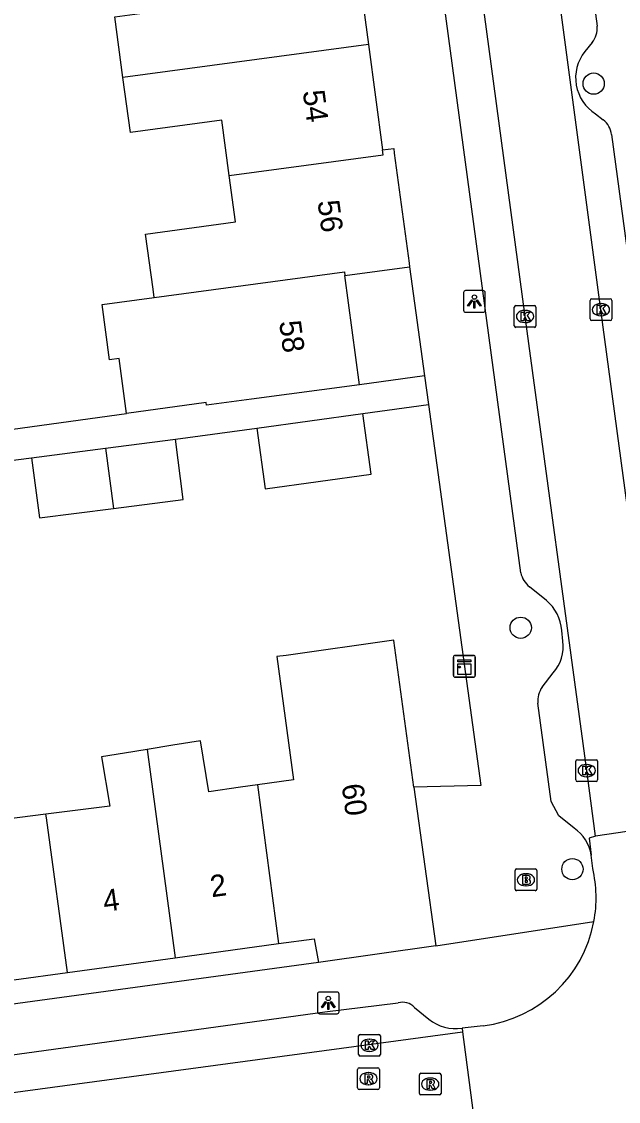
# Model space of a CAD drawing. Extents: x 163150 to 163546, y 380933 to 381635.
# Drawn here: x 163457.89 to 163485.3, y 381316.42 to 381366.01 of the extents above; entities that cross this region are included whole.
import ezdxf

# ---------------------------------------------------------------- set-up
doc = ezdxf.new("R2010")
doc.units = 0
for name, color, linetype in [('IMGEO_Boom', 7, 'Continuous'), ('IMGEO_Brandkraan', 7, 'Continuous'), ('IMGEO_Kast', 7, 'Continuous'), ('IMGEO_Kolk', 7, 'Continuous'), ('IMGEO_Lichtpunt', 7, 'Continuous'), ('IMGEO_Pand', 7, 'Continuous'), ('IMGEO_Pand_nummerreeks', 7, 'Continuous'), ('IMGEO_Rijbaan_lokaal_open', 7, 'Continuous'), ('IMGEO_Rioolput', 7, 'Continuous'), ('IMGEO_Voetpad_open', 7, 'Continuous')]:
    doc.layers.add(name, color=color, linetype=linetype)

msp = doc.modelspace()

# ---------------------------------------------------------------- linework, layer by layer
at = {"layer": 'IMGEO_Boom'}
for centre in [(163484.163, 381363.164), (163480.812, 381338.174), (163483.189, 381327.09)]:
    msp.add_circle(centre, 0.489, dxfattribs=at)
at = {"layer": 'IMGEO_Brandkraan'}
for p, q in [((163480.551, 381326.176), (163480.551, 381327.028)), ((163480.626, 381327.102), (163481.478, 381327.102)), ((163481.039, 381326.882), (163481.064, 381326.882)), ((163481.552, 381327.028), (163481.552, 381326.176)), ((163481.062, 381326.322), (163481.037, 381326.322)), ((163481.478, 381326.102), (163480.626, 381326.102))]:
    msp.add_line(p, q, dxfattribs=at)
for points in [[(163480.551, 381326.176), (163480.551, 381327.028)], [(163480.626, 381327.102), (163481.478, 381327.102)], [(163480.899, 381326.802), (163480.899, 381326.402), (163481.112, 381326.402)], [(163481.13, 381326.802), (163480.899, 381326.802)], [(163481.078, 381326.721), (163481.024, 381326.721), (163481.024, 381326.645)], [(163481.552, 381327.028), (163481.552, 381326.176)], [(163481.024, 381326.645), (163481.077, 381326.645)], [(163481.086, 381326.569), (163481.024, 381326.569), (163481.024, 381326.488)], [(163481.024, 381326.488), (163481.086, 381326.488)], [(163481.478, 381326.102), (163480.626, 381326.102)]]:
    msp.add_lwpolyline(points, dxfattribs=at)
for centre, radius, start, end in [((163480.628, 381327.026), 0.0765, 91.552, 178.448), ((163480.628, 381327.026), 0.0765, 91.552, 178.448), ((163481.079, 381326.683), 0.0379, 267.8285, 90.9355), ((163481.134, 381326.657), 0.145, 59.4692, 91.5367), ((163481.159, 381326.704), 0.0922, 285.5137, 58.1501), ((163481.476, 381327.026), 0.0765, 1.552, 88.448), ((163481.476, 381327.026), 0.0765, 1.552, 88.448), ((163480.628, 381326.178), 0.0765, 181.552, 268.448), ((163480.628, 381326.178), 0.0765, 181.552, 268.448), ((163481.087, 381326.528), 0.0404, 269.8759, 90.5077), ((163481.118, 381326.653), 0.251, 268.6676, 293.5347), ((163481.164, 381326.512), 0.105, 301.3115, 78.989), ((163481.476, 381326.178), 0.0765, 271.552, 358.448), ((163481.476, 381326.178), 0.0765, 271.552, 358.448)]:
    msp.add_arc(centre, radius, start, end, dxfattribs=at)
for centre, major_axis, ratio, start_param, end_param in [((163481.038, 381326.602), (-0.387, 0.002), 0.722429, 4.712389, 7.853982), ((163481.063, 381326.602), (-0.39, 0.002), 0.717154, 1.570796, 4.712389)]:
    msp.add_ellipse(centre, major_axis=major_axis, ratio=ratio, start_param=start_param, end_param=end_param, dxfattribs=at)
at = {"layer": 'IMGEO_Kast'}
for p, q in [((163477.725, 381335.98), (163477.725, 381336.821)), ((163477.725, 381336.821), (163477.725, 381335.98)), ((163477.8, 381336.905), (163478.641, 381336.905)), ((163478.641, 381336.905), (163477.8, 381336.905)), ((163478.725, 381336.83), (163478.725, 381335.989)), ((163478.725, 381335.989), (163478.725, 381336.83)), ((163478.65, 381335.905), (163477.809, 381335.905)), ((163477.809, 381335.905), (163478.65, 381335.905))]:
    msp.add_line(p, q, dxfattribs=at)
for points in [[(163477.92, 381336.695), (163478.52, 381336.695), (163478.52, 381336.61), (163477.92, 381336.61), (163477.92, 381336.695)], [(163477.92, 381336.52), (163478.52, 381336.52), (163478.52, 381336.031), (163477.92, 381336.031), (163477.92, 381336.52)]]:
    msp.add_lwpolyline(points, dxfattribs=at)
msp.add_circle((163478.004, 381336.369), 0.0377, dxfattribs=at)
for centre, start, end in [((163477.803, 381336.827), 92.4484, 184.2845), ((163477.803, 381336.827), 92.4484, 184.2845), ((163478.647, 381336.827), 2.4484, 94.2845), ((163478.647, 381336.827), 2.4484, 94.2845), ((163477.803, 381335.983), 182.4484, 274.2845), ((163477.803, 381335.983), 182.4484, 274.2845), ((163478.647, 381335.983), 272.4484, 4.2845), ((163478.647, 381335.983), 272.4484, 4.2845)]:
    msp.add_arc(centre, 0.0779, start, end, dxfattribs=at)
at = {"layer": 'IMGEO_Kolk'}
for p, q in [((163480.587, 381352.972), (163481.439, 381352.972)), ((163483.996, 381352.357), (163483.996, 381353.209)), ((163484.071, 381353.283), (163484.923, 381353.283)), ((163484.484, 381353.063), (163484.509, 381353.063)), ((163484.997, 381353.209), (163484.997, 381352.357)), ((163480.512, 381352.046), (163480.512, 381352.898)), ((163481, 381352.752), (163481.025, 381352.752)), ((163481.513, 381352.898), (163481.513, 381352.046)), ((163484.507, 381352.503), (163484.482, 381352.503)), ((163481.439, 381351.972), (163480.587, 381351.972)), ((163481.023, 381352.192), (163480.998, 381352.192)), ((163484.923, 381352.283), (163484.071, 381352.283)), ((163483.419, 381332.116), (163484.271, 381332.116)), ((163483.344, 381331.19), (163483.344, 381332.042)), ((163483.832, 381331.896), (163483.857, 381331.896)), ((163484.345, 381332.042), (163484.345, 381331.19)), ((163483.855, 381331.336), (163483.83, 381331.336)), ((163484.271, 381331.116), (163483.419, 381331.116)), ((163473.366, 381318.577), (163473.366, 381319.429)), ((163473.441, 381319.503), (163474.293, 381319.503)), ((163473.854, 381319.283), (163473.879, 381319.283)), ((163474.367, 381319.429), (163474.367, 381318.577)), ((163474.293, 381318.503), (163473.441, 381318.503)), ((163473.877, 381318.723), (163473.852, 381318.723))]:
    msp.add_line(p, q, dxfattribs=at)
for points in [[(163480.587, 381352.972), (163481.439, 381352.972)], [(163483.996, 381352.357), (163483.996, 381353.209)], [(163484.071, 381353.283), (163484.923, 381353.283)], [(163484.317, 381352.983), (163484.44, 381352.983), (163484.44, 381352.832), (163484.57, 381352.983), (163484.734, 381352.983), (163484.588, 381352.832), (163484.741, 381352.583), (163484.589, 381352.583), (163484.504, 381352.747), (163484.44, 381352.68), (163484.44, 381352.583), (163484.317, 381352.583), (163484.317, 381352.983)], [(163484.997, 381353.209), (163484.997, 381352.357)], [(163480.512, 381352.046), (163480.512, 381352.898)], [(163480.833, 381352.672), (163480.956, 381352.672), (163480.956, 381352.521), (163481.086, 381352.672), (163481.25, 381352.672), (163481.104, 381352.521), (163481.257, 381352.272), (163481.105, 381352.272), (163481.02, 381352.436), (163480.956, 381352.369), (163480.956, 381352.272), (163480.833, 381352.272), (163480.833, 381352.672)], [(163481.513, 381352.898), (163481.513, 381352.046)], [(163481.439, 381351.972), (163480.587, 381351.972)], [(163484.923, 381352.283), (163484.071, 381352.283)], [(163483.419, 381332.116), (163484.271, 381332.116)], [(163483.344, 381331.19), (163483.344, 381332.042)], [(163483.665, 381331.816), (163483.788, 381331.816), (163483.788, 381331.665), (163483.918, 381331.816), (163484.082, 381331.816), (163483.936, 381331.665), (163484.089, 381331.416), (163483.937, 381331.416), (163483.852, 381331.58), (163483.788, 381331.513), (163483.788, 381331.416), (163483.665, 381331.416), (163483.665, 381331.816)], [(163484.345, 381332.042), (163484.345, 381331.19)], [(163484.271, 381331.116), (163483.419, 381331.116)], [(163473.366, 381318.577), (163473.366, 381319.429)], [(163473.441, 381319.503), (163474.293, 381319.503)], [(163474.367, 381319.429), (163474.367, 381318.577)], [(163473.687, 381319.203), (163473.81, 381319.203), (163473.81, 381319.052), (163473.94, 381319.203), (163474.104, 381319.203), (163473.958, 381319.052), (163474.111, 381318.803), (163473.959, 381318.803), (163473.874, 381318.967), (163473.81, 381318.9), (163473.81, 381318.803), (163473.687, 381318.803), (163473.687, 381319.203)], [(163474.293, 381318.503), (163473.441, 381318.503)]]:
    msp.add_lwpolyline(points, dxfattribs=at)
for centre, start, end in [((163480.589, 381352.896), 91.552, 178.448), ((163480.589, 381352.896), 91.552, 178.448), ((163481.437, 381352.896), 1.552, 88.448), ((163481.437, 381352.896), 1.552, 88.448), ((163484.073, 381353.207), 91.552, 178.448), ((163484.073, 381353.207), 91.552, 178.448), ((163484.921, 381353.207), 1.552, 88.448), ((163484.921, 381353.207), 1.552, 88.448), ((163480.589, 381352.048), 181.552, 268.448), ((163480.589, 381352.048), 181.552, 268.448), ((163481.437, 381352.048), 271.552, 358.448), ((163481.437, 381352.048), 271.552, 358.448), ((163484.073, 381352.359), 181.552, 268.448), ((163484.073, 381352.359), 181.552, 268.448), ((163484.921, 381352.359), 271.552, 358.448), ((163484.921, 381352.359), 271.552, 358.448), ((163483.421, 381332.04), 91.552, 178.448), ((163483.421, 381332.04), 91.552, 178.448), ((163484.269, 381332.04), 1.552, 88.448), ((163484.269, 381332.04), 1.552, 88.448), ((163483.421, 381331.192), 181.552, 268.448), ((163483.421, 381331.192), 181.552, 268.448), ((163484.269, 381331.192), 271.552, 358.448), ((163484.269, 381331.192), 271.552, 358.448), ((163473.443, 381319.427), 91.552, 178.448), ((163473.443, 381319.427), 91.552, 178.448), ((163474.291, 381319.427), 1.552, 88.448), ((163474.291, 381319.427), 1.552, 88.448), ((163473.443, 381318.579), 181.552, 268.448), ((163473.443, 381318.579), 181.552, 268.448), ((163474.291, 381318.579), 271.552, 358.448), ((163474.291, 381318.579), 271.552, 358.448)]:
    msp.add_arc(centre, 0.0765, start, end, dxfattribs=at)
for centre, major_axis, ratio, start_param, end_param in [((163484.483, 381352.783), (-0.387, 0.002), 0.722429, 4.712389, 7.853982), ((163484.508, 381352.783), (-0.39, 0.002), 0.717154, 1.570796, 4.712389), ((163480.999, 381352.472), (-0.387, 0.002), 0.722429, 4.712389, 7.853982), ((163481.024, 381352.472), (-0.39, 0.002), 0.717154, 1.570796, 4.712389), ((163483.831, 381331.616), (-0.387, 0.002), 0.722429, 4.712389, 7.853982), ((163483.856, 381331.616), (-0.39, 0.002), 0.717154, 1.570796, 4.712389), ((163473.853, 381319.003), (-0.387, 0.002), 0.722429, 4.712389, 7.853982), ((163473.878, 381319.003), (-0.39, 0.002), 0.717154, 1.570796, 4.712389)]:
    msp.add_ellipse(centre, major_axis=major_axis, ratio=ratio, start_param=start_param, end_param=end_param, dxfattribs=at)
at = {"layer": 'IMGEO_Lichtpunt'}
for p, q in [((163478.187, 381353.565), (163478.187, 381352.758)), ((163478.187, 381353.565), (163478.187, 381352.758)), ((163479.089, 381353.66), (163478.281, 381353.66)), ((163479.089, 381353.66), (163478.281, 381353.66)), ((163479.183, 381352.758), (163479.183, 381353.565)), ((163479.183, 381352.758), (163479.183, 381353.565)), ((163478.281, 381352.664), (163479.089, 381352.664)), ((163478.281, 381352.664), (163479.089, 381352.664)), ((163471.475, 381321.352), (163471.475, 381320.545)), ((163471.475, 381321.352), (163471.475, 381320.545)), ((163472.377, 381321.447), (163471.569, 381321.447)), ((163472.377, 381321.447), (163471.569, 381321.447)), ((163472.471, 381320.545), (163472.471, 381321.352)), ((163472.471, 381320.545), (163472.471, 381321.352)), ((163471.569, 381320.451), (163472.377, 381320.451)), ((163471.569, 381320.451), (163472.377, 381320.451))]:
    msp.add_line(p, q, dxfattribs=at)
for points in [[(163478.561, 381353.229), (163478.6, 381353.201), (163478.412, 381352.939), (163478.374, 381352.966), (163478.561, 381353.229)], [(163478.663, 381353.181), (163478.71, 381353.181), (163478.71, 381352.859), (163478.663, 381352.859), (163478.663, 381353.181)], [(163478.773, 381353.201), (163478.811, 381353.228), (163478.998, 381352.966), (163478.959, 381352.938), (163478.773, 381353.201)], [(163471.849, 381321.016), (163471.888, 381320.988), (163471.7, 381320.726), (163471.662, 381320.753), (163471.849, 381321.016)], [(163471.951, 381320.968), (163471.998, 381320.968), (163471.998, 381320.646), (163471.951, 381320.646), (163471.951, 381320.968)], [(163472.061, 381320.988), (163472.099, 381321.015), (163472.286, 381320.753), (163472.247, 381320.725), (163472.061, 381320.988)]]:
    msp.add_lwpolyline(points, dxfattribs=at)
for centre in [(163478.686, 381353.363), (163471.974, 381321.15)]:
    msp.add_circle(centre, 0.0994, dxfattribs=at)
for centre, start, end in [((163478.281, 381353.565), 90, 180), ((163478.281, 381353.565), 90, 180), ((163479.089, 381353.565), 0, 90), ((163479.089, 381353.565), 0, 90), ((163478.281, 381352.758), 180, 270), ((163478.281, 381352.758), 180, 270), ((163479.089, 381352.758), 270, 0), ((163479.089, 381352.758), 270, 360), ((163471.569, 381321.352), 90, 180), ((163471.569, 381321.352), 90, 180), ((163472.377, 381321.352), 0, 90), ((163472.377, 381321.352), 0, 90), ((163471.569, 381320.545), 180, 270), ((163471.569, 381320.545), 180, 270), ((163472.377, 381320.545), 270, 0), ((163472.377, 381320.545), 270, 360)]:
    msp.add_arc(centre, 0.0946, start, end, dxfattribs=at)
at = {"layer": 'IMGEO_Pand'}
for points in [[(163473.176, 381369.742), (163473.819, 381364.957)], [(163462.544, 381363.444), (163462.17, 381366.232), (163466.3, 381366.787), (163466.004, 381368.996)], [(163473.819, 381364.957), (163462.544, 381363.444)], [(163473.819, 381364.957), (163474.469, 381360.117)], [(163467.423, 381358.951), (163467.082, 381361.491), (163462.882, 381360.927), (163462.544, 381363.444)], [(163467.423, 381358.951), (163474.498, 381359.901), (163474.469, 381360.117)], [(163474.469, 381360.117), (163474.977, 381360.185), (163475.006, 381359.969), (163475.685, 381354.914), (163475.706, 381354.758)], [(163463.975, 381353.342), (163463.924, 381353.72), (163463.583, 381356.258), (163467.71, 381356.812), (163467.423, 381358.951)], [(163463.975, 381353.342), (163472.714, 381354.515), (163472.735, 381354.359)], [(163472.735, 381354.359), (163475.706, 381354.758)], [(163473.409, 381349.339), (163472.735, 381354.359)], [(163462.698, 381348.022), (163462.361, 381350.54), (163461.925, 381350.481), (163461.585, 381353.021), (163463.975, 381353.342)], [(163473.409, 381349.339), (163468.454, 381348.674), (163466.379, 381348.395), (163466.365, 381348.514), (163462.698, 381348.022)], [(163468.696, 381347.345), (163473.56, 381348.011)], [(163468.696, 381347.345), (163469.077, 381344.561), (163473.941, 381345.227), (163473.56, 381348.011)], [(163461.745, 381346.425), (163464.952, 381346.84)], [(163462.112, 381343.659), (163465.309, 381344.073), (163464.952, 381346.84)], [(163458.347, 381345.986), (163461.745, 381346.425)], [(163461.745, 381346.425), (163462.112, 381343.659)], [(163458.347, 381345.986), (163458.704, 381343.219), (163462.112, 381343.659)], [(163475.909, 381330.85), (163474.985, 381337.597), (163474.984, 381337.607), (163470.033, 381336.909), (163469.617, 381336.85), (163470.377, 381331.191), (163468.715, 381330.958)], [(163468.715, 381330.958), (163467.946, 381330.85), (163466.49, 381330.646), (163466.108, 381332.987), (163464.833, 381332.779), (163463.652, 381332.586)], [(163463.652, 381332.586), (163462.615, 381332.417), (163461.563, 381332.246), (163461.933, 381329.979), (163459.002, 381329.614)], [(163463.652, 381332.586), (163464.936, 381323.024)], [(163459.002, 381329.614), (163456.595, 381329.314), (163456.289, 381331.521), (163455.14, 381331.361), (163453.75, 381331.168)], [(163468.715, 381330.958), (163469.693, 381323.673)], [(163475.909, 381330.85), (163476.907, 381323.561)], [(163459.992, 381322.35), (163459.024, 381329.451), (163459.002, 381329.614)], [(163469.693, 381323.673), (163471.329, 381323.896), (163471.53, 381322.796)], [(163464.936, 381323.024), (163469.693, 381323.673)], [(163476.907, 381323.561), (163471.53, 381322.796)], [(163459.992, 381322.35), (163464.936, 381323.024)], [(163455.044, 381321.675), (163459.992, 381322.35)]]:
    msp.add_lwpolyline(points, dxfattribs=at)
at = {"layer": 'IMGEO_Rijbaan_lokaal_open'}
for points in [[(163479.013, 381393.424), (163479.069, 381393.155), (163481.839, 381372.532), (163484.475, 381352.776), (163487.265, 381332.107), (163487.676, 381329.103)], [(163484.25, 381328.608), (163483.846, 381331.616), (163481.014, 381352.472), (163478.387, 381372.049), (163475.613, 381392.784), (163475.57, 381392.982)], [(163487.676, 381329.103), (163484.25, 381328.608)], [(163484.25, 381328.608), (163483.954, 381328.514), (163484.055, 381327.735)], [(163484.118, 381327.118), (163484.055, 381327.735)], [(163479.082, 381319.899), (163478.118, 381319.785)], [(163478.118, 381319.785), (163478.14, 381319.616)], [(163422.756, 381312.154), (163478.14, 381319.616)], [(163478.14, 381319.616), (163478.952, 381313.454)]]:
    msp.add_lwpolyline(points, dxfattribs=at)
for centre, radius, start, end in [((163478.37, 381325.767), 5.905, 349.4612, 13.2252), ((163478.363, 381325.767), 5.911, 276.9867, 349.4773)]:
    msp.add_arc(centre, radius, start, end, dxfattribs=at)
at = {"layer": 'IMGEO_Rioolput'}
for p, q in [((163473.32, 381317.042), (163473.32, 381317.894)), ((163473.395, 381317.968), (163474.247, 381317.968)), ((163473.808, 381317.748), (163473.833, 381317.748)), ((163474.321, 381317.894), (163474.321, 381317.042)), ((163476.156, 381316.793), (163476.156, 381317.645)), ((163476.231, 381317.719), (163477.083, 381317.719)), ((163476.644, 381317.499), (163476.669, 381317.499)), ((163477.157, 381317.645), (163477.157, 381316.793)), ((163474.247, 381316.968), (163473.395, 381316.968)), ((163473.831, 381317.188), (163473.806, 381317.188)), ((163476.667, 381316.939), (163476.642, 381316.939)), ((163477.083, 381316.719), (163476.231, 381316.719))]:
    msp.add_line(p, q, dxfattribs=at)
for points in [[(163473.32, 381317.042), (163473.32, 381317.894)], [(163473.395, 381317.968), (163474.247, 381317.968)], [(163474.321, 381317.894), (163474.321, 381317.042)], [(163473.909, 381317.666), (163473.657, 381317.668), (163473.657, 381317.268)], [(163473.657, 381317.268), (163473.781, 381317.268), (163473.781, 381317.43), (163473.792, 381317.43)], [(163473.835, 381317.587), (163473.781, 381317.587), (163473.781, 381317.506)], [(163473.781, 381317.506), (163473.833, 381317.506)], [(163473.839, 381317.401), (163473.91, 381317.268), (163474.05, 381317.268), (163473.985, 381317.394)], [(163476.156, 381316.793), (163476.156, 381317.645)], [(163476.231, 381317.719), (163477.083, 381317.719)], [(163476.745, 381317.417), (163476.493, 381317.419), (163476.493, 381317.019)], [(163476.671, 381317.338), (163476.617, 381317.338), (163476.617, 381317.257)], [(163476.617, 381317.257), (163476.669, 381317.257)], [(163477.157, 381317.645), (163477.157, 381316.793)], [(163474.247, 381316.968), (163473.395, 381316.968)], [(163476.493, 381317.019), (163476.617, 381317.019), (163476.617, 381317.181), (163476.628, 381317.181)], [(163476.675, 381317.152), (163476.746, 381317.019), (163476.886, 381317.019), (163476.821, 381317.145)], [(163477.083, 381316.719), (163476.231, 381316.719)]]:
    msp.add_lwpolyline(points, dxfattribs=at)
for centre, radius, start, end in [((163473.397, 381317.892), 0.0765, 91.552, 178.448), ((163473.397, 381317.892), 0.0765, 91.552, 178.448), ((163474.245, 381317.892), 0.0765, 1.552, 88.448), ((163474.245, 381317.892), 0.0765, 1.552, 88.448), ((163473.791, 381317.377), 0.0533, 26.0293, 88.6989), ((163473.817, 381317.695), 0.19, 274.7715, 282.9687), ((163473.841, 381317.491), 0.0964, 77.0061, 93.1865), ((163473.855, 381317.548), 0.0378, 276.6634, 79.6772), ((163473.908, 381317.556), 0.109, 350.3612, 89.416), ((163473.906, 381317.556), 0.112, 277.5842, 350.9817), ((163473.89, 381317.341), 0.108, 29.5134, 73.7905), ((163476.233, 381317.643), 0.0765, 91.552, 178.448), ((163476.233, 381317.643), 0.0765, 91.552, 178.448), ((163476.653, 381317.446), 0.19, 274.7715, 282.9687), ((163476.677, 381317.242), 0.0964, 77.0061, 93.1865), ((163476.691, 381317.299), 0.0378, 276.6634, 79.6772), ((163476.744, 381317.307), 0.109, 350.3612, 89.416), ((163476.742, 381317.307), 0.112, 277.5842, 350.9817), ((163477.081, 381317.643), 0.0765, 1.552, 88.448), ((163477.081, 381317.643), 0.0765, 1.552, 88.448), ((163473.397, 381317.044), 0.0765, 181.552, 268.448), ((163473.397, 381317.044), 0.0765, 181.552, 268.448), ((163474.245, 381317.044), 0.0765, 271.552, 358.448), ((163474.245, 381317.044), 0.0765, 271.552, 358.448), ((163476.233, 381316.795), 0.0765, 181.552, 268.448), ((163476.233, 381316.795), 0.0765, 181.552, 268.448), ((163476.627, 381317.128), 0.0533, 26.0293, 88.6989), ((163476.726, 381317.092), 0.108, 29.5134, 73.7905), ((163477.081, 381316.795), 0.0765, 271.552, 358.448), ((163477.081, 381316.795), 0.0765, 271.552, 358.448)]:
    msp.add_arc(centre, radius, start, end, dxfattribs=at)
for centre, major_axis, ratio, start_param, end_param in [((163473.807, 381317.468), (-0.387, 0.002), 0.722429, 4.712389, 7.853982), ((163473.832, 381317.468), (-0.39, 0.002), 0.717154, 1.570796, 4.712389), ((163476.643, 381317.219), (-0.387, 0.002), 0.722429, 4.712389, 7.853982), ((163476.668, 381317.219), (-0.39, 0.002), 0.717154, 1.570796, 4.712389)]:
    msp.add_ellipse(centre, major_axis=major_axis, ratio=ratio, start_param=start_param, end_param=end_param, dxfattribs=at)
at = {"layer": 'IMGEO_Voetpad_open'}
for points in [[(163480.813, 381340.703), (163470.252, 381419.099)], [(163480.585, 381393.522), (163484.323, 381365.797)], [(163462.183, 381378.958), (163445.472, 381376.751), (163442.221, 381376.313), (163441.8, 381376.246), (163442.25, 381372.849), (163445.794, 381345.703), (163446.336, 381345.774), (163449.587, 381346.212), (163462.698, 381348.022)], [(163484.09, 381365.053), (163483.758, 381364.638)], [(163484.254, 381361.781), (163484.606, 381361.502)], [(163484.987, 381360.827), (163488.99, 381331.093)], [(163475.706, 381354.758), (163476.394, 381349.749)], [(163476.394, 381349.749), (163473.409, 381349.339)], [(163476.394, 381349.749), (163476.576, 381348.425)], [(163473.56, 381348.011), (163476.576, 381348.425)], [(163476.576, 381348.425), (163478.977, 381330.926), (163475.909, 381330.85)], [(163464.952, 381346.84), (163468.696, 381347.345)], [(163455.225, 381345.582), (163458.347, 381345.986)], [(163481.99, 381339.432), (163481.216, 381340.054)], [(163482.749, 381337.565), (163482.697, 381338.055)], [(163481.795, 381335.449), (163482.303, 381336.105)], [(163483.261, 381328.967), (163482.566, 381329.531), (163482.212, 381330.196), (163481.601, 381334.711)], [(163476.907, 381323.561), (163484.175, 381324.687)], [(163471.53, 381322.796), (163430.746, 381317.253), (163430.452, 381317.213)], [(163424.95, 381314.09), (163471.819, 381320.534), (163475.188, 381320.95)], [(163475.934, 381320.744), (163476.587, 381320.197)]]:
    msp.add_lwpolyline(points, dxfattribs=at)
for centre, radius, start, end in [((163483.273, 381365.717), 1.053, 320.8845, 4.3374), ((163485.274, 381363.43), 1.939, 141.4479, 238.2498), ((163483.963, 381360.694), 1.033, 7.402, 51.4826), ((163481.956, 381340.963), 1.172, 192.8233, 230.8536), ((163480.738, 381337.919), 1.963, 3.96, 50.3951), ((163480.918, 381337.326), 1.847, 318.599, 7.4273), ((163482.766, 381334.799), 1.169, 146.2182, 184.3253), ((163482.286, 381327.467), 1.789, 8.6173, 56.9847), ((163475.38, 381320.193), 0.781, 44.859, 104.2672), ((163477.844, 381321.816), 2.05, 232.1868, 277.6897)]:
    msp.add_arc(centre, radius, start, end, dxfattribs=at)

# ---------------------------------------------------------------- texts
at = {"layer": 'IMGEO_Pand_nummerreeks'}
for s, rotation, p in [('54', 277.6488, (163470.798, 381362.811)), ('56', 277.6488, (163471.477, 381357.756)), ('58', 277.6488, (163469.713, 381352.228)), ('60', 277.7977, (163472.585, 381330.955)), ('2', 7.7693, (163466.615, 381325.796)), ('4', 7.7693, (163461.693, 381325.125))]:
    msp.add_text(s, height=1, rotation=rotation, dxfattribs=at).set_placement(p)

doc.saveas('drawing.dxf')
